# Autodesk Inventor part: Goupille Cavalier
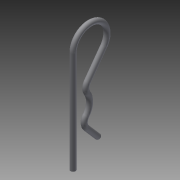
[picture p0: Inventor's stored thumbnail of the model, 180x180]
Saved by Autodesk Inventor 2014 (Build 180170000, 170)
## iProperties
Created: 2015-09
Part Number: Goupille Cavalier
Material: Générique
Document SubType Name: Modeling
Designer: OL
Density: 1 g/cm^3
Appearance: Par défaut
Author: OL
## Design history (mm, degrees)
sketch "Esquisse1"
  geometry: L1 (-10, 0)-(-10, -60); L2 (-1.566, -19.209)-(8.099, -5.866); L3 (-2.215, -42.456)-(4.703, -50.389); A1 r 10 centre (0, 0) between (8.099, -5.866) and (-10, 0); A2 r 9.75 centre (-10, -30) between (-2.363, -36.061) and (-1.749, -24.806); A3 r 5 centre (2.483, -22.142) between (-1.566, -19.209) and (-1.749, -24.806); A4 r 5 centre (1.553, -39.17) between (-2.363, -36.061) and (-2.215, -42.456); 3 further points
  constraints: 10 point on circle, 6 end point, 6 tangent, 4 centre point, 2 point on line, 1 coincident, 1 equal radius, 1 midpoint, 1 vertical
  dimensions: "d0" = 60 vertical distance of L1.end A1.centre; "d2" = 20 diameter of A1; "d4" = 19.5 diameter of A2; "d5" = 5 radius of A3; "d6" = 5.8662 vertical distance of point (0, 0) L2.end; "d7" = 50.3895 vertical distance of point (0, 0) L3.end; "d8" = 4.70303 horizontal distance of point (0, 0) L3.end; "d9" = 2.21517 horizontal distance of point (0, 0) L3.start
sketch "Esquisse2"
  geometry: L1 (0, -10)-(0, 10) reference; C1 r 1.5 at (0, 10); 2 further points
  constraints: 1 centre point, 1 coincident
  dimensions: "d10" = 3 diameter of C1
feature "Balayage1" sketch "Esquisse1", "Esquisse2" dims "d12" = 0
node "Solide1"
other parameters: "d3" = 16
